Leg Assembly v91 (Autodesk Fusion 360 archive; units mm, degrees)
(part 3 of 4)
extrude "Extrude2" cut of existing geometry blind -29.21
extrude "Extrude6" new body sketch "Sketch6" profile of L3 L4 L5 L6 L9 L12 L10 L11 along normal blind 28.4988
work_plane "WorkPlane3" AlongDistance -1.6
split "Split2"
sketch "Sketch7" plane through (0, 0, 26.4) normal (0, 0, 1) x axis (-1, 0, 0)
  line L1 (0.8337, -23.6158) -> (0.8337, 14.8742)
  line L2 (-17.6263, -23.6158) -> (0.8337, -23.6158)
  line L3 (-17.6263, 14.8742) -> (-17.6263, -23.6158)
  line L4 (0.8337, 14.8742) -> (-17.6263, 14.8742)
  line L5 (4.0087, -26.7908) -> (-20.8013, -26.7908)
  line L6 (4.0087, 18.0492) -> (4.0087, -26.7908)
  line L7 (-20.8013, 18.0492) -> (4.0087, 18.0492)
  line L8 (-20.8013, -26.7908) -> (-20.8013, 18.0492)
  line L9 (-20.8013, 6.1292) -> (4.0087, 6.1292)
  line L10 (-20.8013, -1.8708) -> (4.0087, -1.8708)
  circle C1 centre (-8.3963, 6.1292) radius 8.5
  circle C2 centre (-8.3963, 6.1292) radius 8.75
  point P12 (4.0087, 6.1292)
  point P13 (-20.8013, 6.1292)
  point P14 (4.0087, -1.8708)
  point P15 (-20.8013, -1.8708)
  coincident L6 P12
  coincident L8 P13
  perpendicular L8 L9
  coincident L6 P14
  coincident L8 P15
  perpendicular L8 L10
  dimension "d48" = 0.25
  dimension "d51" distance L9 L10 = 8
extrude "Extrude7" add sketch "Sketch7" profile of L1 L3 L4 C2 L10 against normal blind 26.8988
extrude "Extrude8" cut sketch "Sketch7" profile of L4 C2 against normal blind 38.1
offset_faces "OffsetFaces1" distance 0.75
fillet "Fillet3" radius 1.651
split "Split3"
remove_body "RemoveBody5"
mirror "Mirror1" mirrorStitchTolerance 0.1016
combine "Combine2"
component_from_bodies "Body->Comp1"
copy_paste_bodies "CutPasteBodies1"
mirror "Mirror1" mirrorStitchTolerance 0.1016
align "Align1"
extrude "Extrude1" add of existing geometry blind 6.35
extrude "Extrude9" new body of existing geometry blind 19.9898
copy_paste_bodies "CutPasteBodies2"
copy_paste "CutPaste3"
copy_paste_bodies "CutPasteBodies2"
sketch "Sketch8" plane through (0, 0, 19.9956) normal (0, 0, -1) x axis (1, 0, 0)
  line L1 (0.3963, -22.3708) -> (0.3963, -3.3708)
  line L2 (16.3963, -22.3708) -> (0.3963, -22.3708)
  line L3 (16.3963, -3.3708) -> (16.3963, -22.3708)
  line L4 (0.3963, -3.3708) -> (16.3963, -3.3708)
  line L5 (1.5713, -6.5458) -> (1.5713, -21.1958)
  line L6 (15.2213, -6.5458) -> (1.5713, -6.5458)
  line L7 (15.2213, -21.1958) -> (15.2213, -6.5458)
  line L8 (1.5713, -21.1958) -> (15.2213, -21.1958)
  line L9 (-4.0087, 18.0492) -> (20.8013, 18.0492)
  line L10 (-4.0087, -26.7908) -> (-4.0087, 18.0492)
  line L11 (20.8013, -26.7908) -> (-4.0087, -26.7908)
  line L12 (20.8013, 18.0492) -> (20.8013, -26.7908)
  line L13 (16.8763, -22.8658) -> (16.8763, -3.2059)
  line L14 (-0.0837, -22.8658) -> (16.8763, -22.8658)
  line L15 (-0.0837, -3.2059) -> (-0.0837, -22.8658)
  circle C1 centre (8.3963, -14.6208) radius 8
  circle C2 centre (8.3963, -14.6208) radius 8
  arc A1 centre (8.3963, 6.1292) radius 8.75 clockwise from (1.4656, 0.788) to (15.327, 0.788)
  arc A2 centre (16.6347, -0.2198) radius 1.651 clockwise from (15.93, -1.7129) to (15.327, 0.788)
  arc A3 centre (15.2253, -3.2059) radius 1.651 clockwise from (15.93, -1.7129) to (16.8763, -3.2059)
  arc A4 centre (1.5673, -3.2059) radius 1.651 clockwise from (-0.0837, -3.2059) to (0.8626, -1.7129)
  arc A5 centre (0.1579, -0.2198) radius 1.651 clockwise from (1.4656, 0.788) to (0.8626, -1.7129)
  circle C3 centre (8.3963, 6.1292) radius 8.5
  circle C4 centre (8.3963, 6.1292) radius 8.75
  dimension "d72" = 0.25
extrude "Extrude10" new body sketch "Sketch8" profile of L1 L2 L3 L4 L5 L6 L7 L8 C1 C2 A2 A3 L13 L14 L15 A4 A5 C4 along normal blind 5.0038
sketch "Sketch9" plane through (0, 0, 14.9918) normal (0, 0, -1) x axis (1, 0, 0)
  line L1 (-0.0837, -22.8658) -> (-0.0837, -3.2059)
  line L2 (16.8763, -22.8658) -> (-0.0837, -22.8658)
  line L3 (16.8763, -3.2059) -> (16.8763, -22.8658)
  circle C1 centre (8.3963, -14.6208) radius 8
  arc A1 centre (15.2253, -3.2059) radius 1.651 clockwise from (15.93, -1.7129) to (16.8763, -3.2059)
  arc A2 centre (16.6347, -0.2198) radius 1.651 clockwise from (15.93, -1.7129) to (15.327, 0.788)
  arc A3 centre (8.3963, 6.1292) radius 8.75 clockwise from (15.327, 0.788) to (1.4656, 0.788)
  arc A4 centre (0.1579, -0.2198) radius 1.651 clockwise from (1.4656, 0.788) to (0.8626, -1.7129)
  arc A5 centre (1.5673, -3.2059) radius 1.651 clockwise from (-0.0837, -3.2059) to (0.8626, -1.7129)
  arc A6 centre (8.3963, 6.1292) radius 8.75 clockwise from (15.327, 0.788) to (1.4656, 0.788)
  arc A7 centre (8.3963, 6.1292) radius 11.1625 clockwise from (17.2379, -0.6847) to (-0.4452, -0.6847)
  dimension "d73" = 2.4125 (= "0.125 in - 0.0300196850393694 in")
extrude "Extrude11" add sketch "Sketch9" profile of A1 A2 A3 A4 A5 A6 A7 along normal blind 15.4906
combine "Combine3"
delete_face "DeleteFace1"
delete_face "DeleteFace2"
fillet "Fillet1" radius 4.7625
sketch "Sketch10" plane through (0, 0, 8.3168) normal (0, 0, -1) x axis (1, 0, 0)
  circle C1 centre (8.3963, -14.6208) radius 4
  circle C2 centre (8.3963, -14.6208) radius 8
  circle C3 centre (8.3963, -14.6208) radius 9.5875
  dimension "d78" = 1.5875 (= "( 1 / 16 ) * 1 in")
extrude "Extrude7" cut sketch "Sketch10" along normal blind 15.24 and against normal blind 6.6802
extrude "Extrude8" add of existing geometry blind 0.0052 (= "2.047E-04 in")
sketch "Sketch11" plane through (0, 0, 14.9918) normal (0, 0, -1) x axis (1, 0, 0)
  line L1 (16.8763, -22.8658) -> (13.2892, -22.8658)
  line L2 (16.8763, -19.0941) -> (16.8763, -22.8658)
  line L3 (16.8763, -9.3559) -> (16.8763, -10.1476)
  line L4 (-0.0837, -10.1476) -> (-0.0837, -9.3559)
  line L5 (-0.0837, -22.8658) -> (-0.0837, -19.0941)
  line L6 (3.5034, -22.8658) -> (-0.0837, -22.8658)
  circle C1 centre (8.3963, -14.6208) radius 8
  arc A1 centre (8.3963, -14.6208) radius 9.5875 clockwise from (16.8763, -10.1476) to (16.8763, -19.0941)
  arc A2 centre (12.1138, -9.3559) radius 4.7625 clockwise from (11.0021, -4.7249) to (16.8763, -9.3559)
  arc A3 centre (8.3963, 6.1292) radius 11.1625 clockwise from (11.0021, -4.7249) to (5.7906, -4.7249)
  arc A4 centre (4.6788, -9.3559) radius 4.7625 clockwise from (-0.0837, -9.3559) to (5.7906, -4.7249)
  arc A5 centre (8.3963, -14.6208) radius 9.5875 clockwise from (-0.0837, -19.0941) to (-0.0837, -10.1476)
  arc A6 centre (8.3963, -14.6208) radius 9.5875 clockwise from (13.2892, -22.8658) to (3.5034, -22.8658)
  circle C2 centre (8.3963, -14.6208) radius 9.5875
  dimension "d85" = 1.5875 (= "( 1 / 16 ) * 1 in")
extrude "Extrude9" add sketch "Sketch11" profile of L1 L2 L3 A2 A3 A4 L4 L5 L6 C2 along normal blind 15.494
extrude "Extrude10" cut of existing geometry blind -0.0034 (= "-1.339E-04 in")
extrude "Extrude3" cut of existing geometry blind -0.508
extrude "Extrude11" cut of existing geometry blind -0.508
extrude "Extrude4" cut of existing geometry blind -1
offset_faces "OffsetFaces1" distance 1.5875 (= "( 1 / 16 ) * 1 in")
split "Split2"
delete_face "DeleteFace3"
combine "Combine4"
split "Split3"
sketch "Sketch12" plane through (0, 0, 4.8168) normal (0, 0, 1) x axis (-1, 0, 0)
  line L1 (-4.6463, -6.3208) -> (-1.1463, -9.8208)
  line L2 (-12.1463, -6.3208) -> (-4.6463, -6.3208)
  line L3 (-15.6463, -9.8208) -> (-12.1463, -6.3208)
  line L4 (-15.6463, -13.7917) -> (-15.6463, -9.8208)
  line L5 (-15.6463, -19.8208) -> (-15.6463, -15.45)
  line L6 (-1.1463, -15.45) -> (-1.1463, -19.8208)
  line L7 (-1.1463, -9.8208) -> (-1.1463, -13.7917)
  line L8 (-12.1463, -6.3208) -> (-15.6463, -9.8208)
  line L9 (-4.6463, -6.3208) -> (-12.1463, -6.3208)
  line L10 (-4.6463, -6.3208) -> (-1.1463, -9.8208)
  line L11 (-15.6463, -9.8208) -> (-15.6463, -19.8208)
  line L12 (-1.1463, -9.8208) -> (-1.1463, -19.8208)
  line L13 (-0.8963, -9.7173) -> (-0.8963, -19.8925)
  line L14 (-4.5428, -6.0708) -> (-0.8963, -9.7173)
  line L15 (-4.5428, -6.0708) -> (-12.2499, -6.0708)
  line L16 (-12.2499, -6.0708) -> (-15.8963, -9.7173)
  line L17 (-15.8963, -9.7173) -> (-15.8963, -19.8925)
  arc A1 centre (-14.3963, -14.6208) radius 1.5 clockwise from (-15.6463, -13.7917) to (-15.6463, -15.45)
  arc A2 centre (-8.3963, -15.2505) radius 8.5703 clockwise from (-1.1463, -19.8208) to (-15.6463, -19.8208)
  arc A3 centre (-2.3963, -14.6208) radius 1.5 clockwise from (-1.1463, -15.45) to (-1.1463, -13.7917)
  arc A4 centre (-8.3963, -15.2505) radius 8.5703 clockwise from (-1.1463, -19.8208) to (-15.6463, -19.8208)
  arc A5 centre (-8.3963, -15.2505) radius 8.8203 clockwise from (-0.8963, -19.8925) to (-15.8963, -19.8925)
  circle C1 centre (-8.3963, -14.6208) radius 9.5875
  point P15 (-15.6463, -19.8208)
  point P22 (-15.6463, -19.8208)
  point P18 (-15.6463, -9.8208)
  point P23 (-15.6463, -9.8208)
  point P16 (-1.1463, -19.8208)
  point P24 (-1.1463, -19.8208)
  point P21 (-1.1463, -9.8208)
  point P25 (-1.1463, -9.8208)
  coincident P15 P22
  coincident P18 P23
  coincident P16 P24
  coincident P21 P25
  dimension "d97" = 0.25
extrude "Extrude12" add sketch "Sketch12" profile of A5 L13 L14 L15 L16 L17 C1 against normal blind 4.8006
extrude "Extrude13" add of existing geometry blind 0.007 (= "2.756E-04 in")
split "Split4"
delete_face "DeleteFace4"
delete_face "DeleteFace5"
combine "Combine5"
extrude "Extrude14" add of existing geometry blind 1.4986
extrude "Extrude15" add of existing geometry blind 0.0014 (= "5.512E-05 in")
sketch "Sketch13" plane through (0, 0, 6.3168) normal (0, 0, 1) x axis (-1, 0, 0)
  line L1 (-15.8963, -9.7173) -> (-15.8963, -19.8925)
  line L2 (-12.2499, -6.0708) -> (-15.8963, -9.7173)
  line L3 (-4.5428, -6.0708) -> (-12.2499, -6.0708)
  line L4 (-0.8963, -9.7173) -> (-4.5428, -6.0708)
  line L5 (-0.8963, -19.8925) -> (-0.8963, -9.7173)
  line L6 (5.5962, 19.6367) -> (5.5962, -28.3783)
  line L7 (-22.3888, 19.6367) -> (5.5962, 19.6367)
  line L8 (-22.3888, -28.3783) -> (-22.3888, 19.6367)
  line L9 (5.5962, -28.3783) -> (-22.3888, -28.3783)
  line L10 (-3.6338, -52.7208) -> (-13.1588, -52.7208)
  line L11 (-3.6338, 23.4792) -> (-3.6338, -52.7208)
  line L12 (-13.1588, 23.4792) -> (-3.6338, 23.4792)
  line L13 (-13.1588, -52.7208) -> (-13.1588, 23.4792)
  line L14 (-3.6338, 23.4792) -> (-13.1588, -52.7208)
  line L15 (-13.1588, 23.4792) -> (-3.6338, -52.7208)
  arc A1 centre (-8.3963, -15.2505) radius 8.8203 clockwise from (-0.8963, -19.8925) to (-15.8963, -19.8925)
  circle C1 centre (-8.3963, 6.1292) radius 8.75
  circle C2 centre (-8.3963, -14.6208) radius 4
  point P19 (-8.3963, -14.6208)
  point P14 (-8.3963, -14.6208)
  point P15 (-13.1588, -52.7208)
  point P16 (-3.6338, -52.7208)
  point P18 (-13.1588, 23.4792)
  horizontal L10
  perpendicular L10 L11
  parallel L10 L12
  parallel L11 L13
  coincident L14 P19
  coincident L15 P19
  coincident P14 P19
  dimension "d106" distance P15 P16 = 9.525
  dimension "d107" distance P15 P18 = 76.2
extrude "Extrude16" cut sketch "Sketch13" profile of A1 L9 L11 L13 against normal blind 3.2004
extrude "Extrude17" cut sketch "Sketch13" profile of L7 C1 L11 L13 against normal blind 5.3086
extrude "Extrude18" cut of existing geometry blind -0.0002 (= "-7.873E-06 in")
extrude "Extrude19" add of existing geometry blind 0.0004 (= "1.574E-05 in")
combine "Combine1"
offset_faces "OffsetFaces2" distance 0.7937 (= "( 1 / 32 ) * 1 in")
extrude "Extrude20" add of existing geometry blind 2.175 (= "0.125 in - 1 mm")
sketch "Sketch14" plane through (0, 0, 28) normal (0, 0, 1) x axis (-1, 0, 0)
  line L1 (0.8337, 14.8742) -> (-17.6263, 14.8742)
  line L2 (0.8337, -23.6158) -> (0.8337, 14.8742)
  line L3 (-17.6263, -23.6158) -> (0.8337, -23.6158)
  line L4 (-17.6263, 14.8742) -> (-17.6263, -23.6158)
  line L5 (-22.3888, -28.3783) -> (-22.3888, 19.6367)
  line L6 (5.5962, -28.3783) -> (-22.3888, -28.3783)
  line L7 (5.5962, 19.6367) -> (5.5962, -28.3783)
  line L8 (-22.3888, 19.6367) -> (5.5962, 19.6367)
  line L9 (-17.6963, 15.5831) -> (0.9037, 15.5831)
  line L10 (0.9037, 15.5831) -> (-17.6963, 15.5831)
  line L11 (-18.3963, -23.3708) -> (-18.3963, 14.6292)
  line L12 (-18.3963, -17.3601) -> (-18.3963, -23.3708)
  line L13 (-18.3963, -4.3708) -> (-18.3963, -17.3601)
  line L14 (-18.3963, 14.6292) -> (-18.3963, -4.3708)
  line L15 (1.6037, 14.6292) -> (1.6037, -23.3708)
  line L16 (1.6037, -4.3708) -> (1.6037, 14.6292)
  line L17 (1.6037, -17.3601) -> (1.6037, -4.3708)
  line L18 (1.6037, -23.3708) -> (1.6037, -17.3601)
  line L19 (-17.6963, -24.3248) -> (0.9037, -24.3248)
  line L20 (0.9037, -24.3248) -> (-17.6963, -24.3248)
  arc A1 centre (-17.3963, 14.6292) radius 1 clockwise from (-18.3963, 14.6292) to (-17.6963, 15.5831)
  arc A2 centre (-17.3963, 14.6292) radius 1 clockwise from (-18.3963, 14.6292) to (-17.6963, 15.5831)
  arc A3 centre (0.6037, 14.6292) radius 1 clockwise from (0.9037, 15.5831) to (1.6037, 14.6292)
  arc A4 centre (0.6037, 14.6292) radius 1 clockwise from (0.9037, 15.5831) to (1.6037, 14.6292)
  arc A5 centre (0.6037, -23.3708) radius 1 clockwise from (1.6037, -23.3708) to (0.9037, -24.3248)
  arc A6 centre (0.6037, -23.3708) radius 1 clockwise from (1.6037, -23.3708) to (0.9037, -24.3248)
  arc A7 centre (-17.3963, -23.3708) radius 1 clockwise from (-17.6963, -24.3248) to (-18.3963, -23.3708)
  arc A8 centre (-17.3963, -23.3708) radius 1 clockwise from (-17.6963, -24.3248) to (-18.3963, -23.3708)
extrude "Extrude21" add sketch "Sketch14" profile of L5 L6 L7 L8 A1 A2 L9 L10 L11 L12 L13 L14 A3 A4 L15 L16 L17 L18 A5 A6 L19 L20 A7 A8 along normal blind 13.0048
split "Split5"
extrude "Extrude22" add of existing geometry blind 2
remove_body "RemoveBody3"
copy_paste "CutPaste1"
copy_paste_bodies "CutPasteBodies1"
remove_instance "RemoveInstance2"
split "Split6"
remove_body "RemoveBody4"
combine "Combine1"
offset_faces "OffsetFaces3" distance 4.93 (= "0.1315944881889787 in + ( 1 / 16 ) * 1 in")
sketch "Sketch16" plane through (0, 0, 28) normal (0, 0, 1) x axis (-1, 0, 0)
  line L1 (5.5962, 24.5667) -> (5.5962, -33.3083)
  line L2 (-22.3888, 24.5667) -> (5.5962, 24.5667)
  line L3 (-22.3888, -33.3083) -> (-22.3888, 24.5667)
  line L4 (5.5962, -33.3083) -> (-22.3888, -33.3083)
  line L5 (0.8337, 14.8742) -> (-17.6263, 14.8742)
  line L6 (0.8337, -23.6158) -> (0.8337, 14.8742)
  line L7 (-17.6263, -23.6158) -> (0.8337, -23.6158)
  line L8 (-17.6263, 14.8742) -> (-17.6263, -23.6158)
  arc A1 centre (-3.4963, 20.4292) radius 2.1 clockwise from (-2.4963, 22.2758) to (-4.4963, 22.2758)
  circle C1 centre (-3.4963, 20.4292) radius 1.5
  concentric A1 C1
  dimension "d141" diameter C1 = 3
work_plane "WorkPlane5"
chamfer "Chamfer1" distance 6.35
split "Split7"
sketch "Sketch17" plane through (0, 0, 28) normal (0, 0, 1) x axis (-1, 0, 0)
  line L1 (0.8337, 14.8742) -> (-17.6263, 14.8742)
  line L2 (0.8337, -23.6158) -> (0.8337, 14.8742)
  line L3 (-17.6263, -23.6158) -> (0.8337, -23.6158)
  line L4 (-17.6263, 14.8742) -> (-17.6263, -23.6158)
  line L5 (5.5962, -26.9583) -> (-0.7538, -33.3083)
  line L6 (5.5962, 18.2167) -> (5.5962, -26.9583)
  line L7 (-0.7538, 24.5667) -> (5.5962, 18.2167)
  line L8 (-16.0388, 24.5667) -> (-0.7538, 24.5667)
  line L9 (-22.3888, 18.2167) -> (-16.0388, 24.5667)
  line L10 (-22.3888, -26.9583) -> (-22.3888, 18.2167)
  line L11 (-16.0388, -33.3083) -> (-22.3888, -26.9583)
  line L12 (-0.7538, -33.3083) -> (-16.0388, -33.3083)
  arc A1 centre (-3.4963, 20.4292) radius 2.1 clockwise from (-2.4963, 22.2758) to (-4.4963, 22.2758)
  circle C1 centre (-3.4963, 20.4292) radius 2.2
  concentric A1 C1
  dimension "d149" diameter C1 = 4.4
extrude "Extrude26" cut sketch "Sketch17" profile of C1 against normal blind 6
mirror "Mirror4" mirrorStitchTolerance 0.1016
mirror "Mirror5" mirrorStitchTolerance 0.1016
sketch "Sketch1" plane through (0, 0, 0) normal (0, 0, 1) x axis (1, 0, 0)
  circle C1 centre (0, 0) radius 2.45
  circle C2 centre (0, 0) radius 1.5
  circle C3 centre (0, 0) radius 1.95
  point P1 (0, 0)
  point P2 (0, 0)
  coincident P1 P2
  concentric C1 C2
  concentric C1 C3
  dimension "d1_2" diameter C1 = 4.9
  dimension "d2_2" diameter C2 = 3
  dimension "d3_2" diameter C3 = 3.9
extrude "Extrude1" new body sketch "Sketch1" distance 0.7 (= "( 1.4 / 2 ) * 1 mm") named "d4_2"
extrude "Extrude2" add sketch "Sketch1" profile of C2 C3 distance 3.3 (= "5 mm - 1.7 mm") named "d6_2"
extrude "Extrude3" of existing geometry blind 1.7 named "d9_2"
extrude "Extrude4" add of existing geometry blind 1.7 named "d11_2"
mirror "Mirror1" mirrorStitchTolerance 0.1 named "d14_1"
extrude "Extrude5" new body sketch "Sketch1" profile of C2 C3 distance 3 named "d15_1"
extrude "Extrude6" sketch "Sketch1" blind -1.8 named "d18_1"
mirror "Mirror2" mirrorStitchTolerance 0.1 named "d21_1"
move "Move1"
copy_paste "CutPaste4"
remove_body "RemoveBody1"
align "Align1"
mirror "Mirror3" mirrorStitchTolerance 0.1016
mirror "Mirror4" mirrorStitchTolerance 0.1016
base_feature "Base Feature1"
base_feature "Base Feature1"
base_feature "Base Feature1"
base_feature "Base Feature1"
base_feature "Base Feature1"
base_feature "Base Feature1"
copy_paste "CutPaste5"
remove_instance "RemoveInstance4"
align "Align1"
mirror "Mirror1" mirrorStitchTolerance 0.1016
mirror "Mirror2" mirrorStitchTolerance 0.1016
sketch "Sketch18" plane through (0, 0, -2.1658) normal (0, 0, -1) x axis (1, 0, 0)
  line L1 (0.7538, -33.3083) -> (-5.5962, -26.9583)
  line L2 (16.0388, -33.3083) -> (0.7538, -33.3083)
  line L3 (22.3888, -26.9583) -> (16.0388, -33.3083)
  line L4 (22.3888, 18.2167) -> (22.3888, -26.9583)
  line L5 (16.0388, 24.5667) -> (22.3888, 18.2167)
  line L6 (0.7538, 24.5667) -> (16.0388, 24.5667)
  line L7 (-5.5962, 18.2167) -> (0.7538, 24.5667)
  line L8 (-5.5962, -26.9583) -> (-5.5962, 18.2167)
  line L9 (-5.5962, -26.9583) -> (0.7538, -33.3083)
  line L10 (-5.5962, 18.2167) -> (-5.5962, -26.9583)
  line L11 (0.7538, 24.5667) -> (-5.5962, 18.2167)
  line L12 (3.6338, 24.5667) -> (0.7538, 24.5667)
  line L13 (3.6338, 13.4695) -> (3.6338, 24.5667)
  line L14 (13.1588, 24.5667) -> (13.1588, 13.4695)
  line L15 (16.0388, 24.5667) -> (13.1588, 24.5667)
  line L16 (22.3888, 18.2167) -> (16.0388, 24.5667)
  line L17 (22.3888, -26.9583) -> (22.3888, 18.2167)
  line L18 (16.0388, -33.3083) -> (22.3888, -26.9583)
  line L19 (13.1588, -33.3083) -> (16.0388, -33.3083)
  line L20 (13.1588, -22.6746) -> (13.1588, -33.3083)
  line L21 (15.8963, -9.7173) -> (15.8963, -19.8925)
  line L22 (12.2499, -6.0708) -> (15.8963, -9.7173)
  line L23 (4.5428, -6.0708) -> (12.2499, -6.0708)
  line L24 (0.8963, -9.7173) -> (4.5428, -6.0708)
  line L25 (0.8963, -19.8925) -> (0.8963, -9.7173)
  line L26 (3.6338, -33.3083) -> (3.6338, -22.6746)
  line L27 (0.7538, -33.3083) -> (3.6338, -33.3083)
  line L28 (-5.5962, -26.9583) -> (22.3888, 18.2167)
  line L29 (-5.5962, 18.2167) -> (22.3888, -26.9583)
  line L30 (-1.1287, -25.0083) -> (17.9213, -25.0083)
  line L31 (-1.1287, 16.2667) -> (-1.1287, -25.0083)
  line L32 (17.9213, 16.2667) -> (-1.1287, 16.2667)
  line L33 (17.9213, -25.0083) -> (17.9213, 16.2667)
  line L34 (-1.1287, 16.2667) -> (17.9213, -25.0083)
  line L35 (17.9213, 16.2667) -> (-1.1287, -25.0083)
  arc A1 centre (8.3963, 6.1292) radius 8.75 clockwise from (13.1588, 13.4695) to (3.6338, 13.4695)
  arc A2 centre (8.3963, -15.2505) radius 8.8203 clockwise from (15.8963, -19.8925) to (13.1588, -22.6746)
  arc A3 centre (8.3963, -15.2505) radius 8.8203 clockwise from (3.6338, -22.6746) to (0.8963, -19.8925)
  circle C1 centre (17.9213, 16.2667) radius 2.2
  point P20 (22.3888, 18.2167)
  point P34 (22.3888, 18.2167)
  point P11 (-5.5962, -26.9583)
  point P35 (-5.5962, -26.9583)
  point P21 (22.3888, -26.9583)
  point P36 (22.3888, -26.9583)
  point P12 (-5.5962, 18.2167)
  point P37 (-5.5962, 18.2167)
  point P38 (8.3963, -4.3708)
  point P43 (8.3963, -4.3708)
  point P42 (17.9213, 16.2667)
  point P44 (17.9213, 16.2667)
  point P39 (17.9213, -25.0083)
  point P41 (-1.1287, 16.2667)
  coincident P20 P34
  coincident P11 P35
  coincident P21 P36
  coincident P12 P37
  midpoint L29 P38
  horizontal L30
  perpendicular L30 L31
  parallel L30 L32
  parallel L31 L33
  coincident L34 P43
  coincident L35 P43
  coincident P38 P43
  coincident P42 P44
  dimension "d164" distance P39 P42 = 41.275
  dimension "d165" distance P41 P42 = 19.05
  dimension "d166" diameter C1 = 4.4
extrude "Extrude27" cut sketch "Sketch18" profile of C1 against normal blind 6
mirror "Mirror6" mirrorStitchTolerance 0.1016
mirror "Mirror7" mirrorStitchTolerance 0.1016
copy_paste_bodies "CopyPasteBodies1"
move "Move2"
align "Align2"
mirror "Mirror5" mirrorStitchTolerance 0.1016
mirror "Mirror6" mirrorStitchTolerance 0.1016
offset_faces "OffsetFaces4" distance 0.7937 (= "( 1 / 32 ) * 1 in")
delete_face "DeleteFace8"
delete_face "DeleteFace9"
delete_face "DeleteFace10"
delete_face "DeleteFace11"
delete_face "DeleteFace12"
delete_face "DeleteFace13"
delete_face "DeleteFace14"
delete_face "DeleteFace15"
chamfer "Chamfer2" distance 6.35
sketch "Sketch19" plane through (0, 0, 8.3168) normal (0, 0, 1) x axis (-1, 0, 0)
  line L1 (-16.8326, -34.1021) -> (-23.1826, -27.7521)
  line L2 (-13.1588, -34.1021) -> (-16.8326, -34.1021)
  line L3 (-13.1588, -22.6746) -> (-13.1588, -34.1021)
  line L4 (-15.8963, -9.7173) -> (-15.8963, -19.8925)
  line L5 (-12.2499, -6.0708) -> (-15.8963, -9.7173)
  line L6 (-4.5428, -6.0708) -> (-12.2499, -6.0708)
  line L7 (-0.8963, -9.7173) -> (-4.5428, -6.0708)
  line L8 (-0.8963, -19.8925) -> (-0.8963, -9.7173)
  line L9 (-3.6338, -34.1021) -> (-3.6338, -22.6746)
  line L10 (0.0399, -34.1021) -> (-3.6338, -34.1021)
  line L11 (6.3899, -27.7521) -> (0.0399, -34.1021)
  line L12 (6.3899, 19.0104) -> (6.3899, -27.7521)
  line L13 (0.0399, 25.3604) -> (6.3899, 19.0104)
  line L14 (-3.6338, 25.3604) -> (0.0399, 25.3604)
  line L15 (-3.6338, 13.4695) -> (-3.6338, 25.3604)
  line L16 (-13.1588, 25.3604) -> (-13.1588, 13.4695)
  line L17 (-16.8326, 25.3604) -> (-13.1588, 25.3604)
  line L18 (-23.1826, 19.0104) -> (-16.8326, 25.3604)
  line L19 (-23.1826, -27.7521) -> (-23.1826, 19.0104)
  line L20 (-14.7463, -14.6208) -> (-2.0463, -14.6208)
  arc A1 centre (-8.3963, -15.2505) radius 8.8203 clockwise from (-13.1588, -22.6746) to (-15.8963, -19.8925)
  arc A2 centre (-8.3963, -15.2505) radius 8.8203 clockwise from (-0.8963, -19.8925) to (-3.6338, -22.6746)
  arc A3 centre (-8.3963, 6.1292) radius 8.75 clockwise from (-3.6338, 13.4695) to (-13.1588, 13.4695)
  circle C1 centre (-8.3963, -14.6208) radius 4
  arc A4 centre (-7.6763, -14.8049) radius 9.6671 clockwise from (-15.8963, -19.8925) to (-15.8963, -9.7173)
  arc A5 centre (-9.1163, -14.8049) radius 9.6671 clockwise from (-0.8963, -9.7173) to (-0.8963, -19.8925)
  point P26 (-8.3963, -14.6208)
  point P29 (-8.3963, -14.6208)
  point P6 (-15.8963, -19.8925)
  point P31 (-15.8963, -19.8925)
  point P8 (-15.8963, -9.7173)
  point P30 (-15.8963, -9.7173)
  point P11 (-0.8963, -9.7173)
  point P34 (-0.8963, -9.7173)
  point P12 (-0.8963, -19.8925)
  point P33 (-0.8963, -19.8925)
  point P27 (-2.0463, -14.6208)
  point P28 (-14.7463, -14.6208)
  perpendicular L4 L20
  coincident P26 P29
  midpoint L20 P29
  coincident P6 P31
  coincident P8 P30
  coincident P11 P34
  coincident P12 P33
  tangent A1 A4
  tangent A2 A5
  dimension "d179" distance P27 P28 = 12.7
extrude "Extrude28" cut sketch "Sketch19" profile of L4 L8 A4 A5 against normal blind 2
sketch "Sketch20" plane through (0, 0, 26.4) normal (0, 0, 1) x axis (-1, 0, 0)
  line L1 (-17.6263, 14.8742) -> (-8.6921, 14.8742)
  line L2 (-17.6263, -23.6158) -> (-17.6263, 14.8742)
  line L3 (0.8337, -23.6158) -> (-17.6263, -23.6158)
  line L4 (0.8337, 14.8742) -> (0.8337, -23.6158)
  line L5 (-8.1005, 14.8742) -> (0.8337, 14.8742)
  line L6 (0.0837, -22.8658) -> (0.0837, -3.2059)
  line L7 (-16.8763, -22.8658) -> (0.0837, -22.8658)
  line L8 (-16.8763, -3.2059) -> (-16.8763, -22.8658)
  line L9 (-16.8763, 12.104) -> (-16.8763, -3.2059)
  line L10 (0.0837, 11.1729) -> (0.0837, -3.2059)
  arc A1 centre (-8.3963, 6.1292) radius 8.75 clockwise from (-8.1005, 14.8742) to (-1.4656, 0.788)
  arc A2 centre (-0.1579, -0.2198) radius 1.651 clockwise from (-0.8626, -1.7129) to (-1.4656, 0.788)
  arc A3 centre (-1.5673, -3.2059) radius 1.651 clockwise from (-0.8626, -1.7129) to (0.0837, -3.2059)
  arc A4 centre (-15.2253, -3.2059) radius 1.651 clockwise from (-16.8763, -3.2059) to (-15.93, -1.7129)
  arc A5 centre (-16.6347, -0.2198) radius 1.651 clockwise from (-15.327, 0.788) to (-15.93, -1.7129)
  arc A6 centre (-8.3963, 6.1292) radius 8.75 clockwise from (-15.327, 0.788) to (-8.6921, 14.8742)
  point P16 (-16.8763, -3.2059)
  point P21 (-16.8763, -3.2059)
  point P12 (0.0837, -3.2059)
  point P23 (0.0837, -3.2059)
  coincident P16 P21
  tangent A4 L9
  coincident P12 P23
  tangent A3 L10
extrude "Extrude29" cut sketch "Sketch20" profile of A1 A2 A3 A4 A5 A6 L9 L10 against normal blind 6.4008
extrude "Extrude30" cut of existing geometry blind -0.0036 (= "-1.417E-04 in")
component_from_bodies "Body->Comp1"
component_from_bodies "Body->Comp2"
component_from_bodies "Body->Comp3"
sketch "Sketch21" plane through (0, 0, 8.3168) normal (0, 0, 1) x axis (-1, 0, 0)
  line L1 (-3.6338, -34.1021) -> (-3.6338, -22.6746)
  line L2 (0.0399, -34.1021) -> (-3.6338, -34.1021)
  line L3 (6.3899, -27.7521) -> (0.0399, -34.1021)
  line L4 (6.3899, 19.0104) -> (6.3899, -27.7521)
  line L5 (0.0399, 25.3604) -> (6.3899, 19.0104)
  line L6 (-3.6338, 25.3604) -> (0.0399, 25.3604)
  line L7 (-3.6338, 13.4695) -> (-3.6338, 25.3604)
  line L8 (-13.1588, 25.3604) -> (-13.1588, 13.4695)
  line L9 (-16.8326, 25.3604) -> (-13.1588, 25.3604)
  line L10 (-23.1826, 19.0104) -> (-16.8326, 25.3604)
  line L11 (-23.1826, -27.7521) -> (-23.1826, 19.0104)
  line L12 (-16.8326, -34.1021) -> (-23.1826, -27.7521)
  line L13 (-13.1588, -34.1021) -> (-16.8326, -34.1021)
  line L14 (-13.1588, -22.6746) -> (-13.1588, -34.1021)
  line L15 (-12.2499, -6.0708) -> (-15.8963, -9.7173)
  line L16 (-4.5428, -6.0708) -> (-12.2499, -6.0708)
  line L17 (-0.8963, -9.7173) -> (-4.5428, -6.0708)
  line L18 (-0.8963, -9.7173) -> (-0.8963, -19.8925)
  line L19 (-4.5428, -6.0708) -> (-0.8963, -9.7173)
  line L20 (-12.2499, -6.0708) -> (-4.5428, -6.0708)
  line L21 (-15.8963, -9.7173) -> (-12.2499, -6.0708)
  line L22 (-15.8963, -19.8925) -> (-15.8963, -9.7173)
  line L23 (-13.1588, -34.1021) -> (-13.1588, -22.6746)
  line L24 (-3.6338, -34.1021) -> (-13.1588, -34.1021)
  line L25 (-3.6338, -22.6746) -> (-3.6338, -34.1021)
  arc A1 centre (-9.1163, -14.8049) radius 9.6671 clockwise from (-0.8963, -9.7173) to (-0.8963, -19.8925)
  arc A2 centre (-8.3963, -15.2505) radius 8.8203 clockwise from (-0.8963, -19.8925) to (-3.6338, -22.6746)
  arc A3 centre (-8.3963, 6.1292) radius 8.75 clockwise from (-3.6338, 13.4695) to (-13.1588, 13.4695)
  arc A4 centre (-8.3963, -15.2505) radius 8.8203 clockwise from (-13.1588, -22.6746) to (-15.8963, -19.8925)
  arc A5 centre (-7.6763, -14.8049) radius 9.6671 clockwise from (-15.8963, -19.8925) to (-15.8963, -9.7173)
  arc A6 centre (-8.3963, -15.2505) radius 8.5703 clockwise from (-1.1463, -19.8208) to (-15.6463, -19.8208)
  arc A7 centre (-8.3963, -15.2505) radius 8.8203 clockwise from (-3.6338, -22.6746) to (-13.1588, -22.6746)
  arc A8 centre (-8.3963, -15.2505) radius 8.8203 clockwise from (-13.1588, -22.6746) to (-15.8963, -19.8925)
  arc A9 centre (-8.3963, -15.2505) radius 8.8203 clockwise from (-0.8963, -19.8925) to (-3.6338, -22.6746)
  point P22 (-13.1588, -22.6746)
  point P32 (-13.1588, -22.6746)
  point P5 (-3.6338, -22.6746)
  point P31 (-3.6338, -22.6746)
  coincident P22 P32
  coincident P5 P31
  tangent A4 A7
extrude "Extrude1" add sketch "Sketch21" profile of L1 L14 A7 L23 L24 L25 against normal blind 5.207
move_face "MoveFace1"
position "Position5"
sketch "Sketch22" plane through (0, 0, 8.3168) normal (0, 0, 1) x axis (-1, 0, 0)
  line L1 (0.1537, -10.7673) -> (-3.4928, -7.1208)
  line L2 (0.1537, -18.4744) -> (0.1537, -10.7673)
  line L3 (-3.4928, -22.1208) -> (0.1537, -18.4744)
  line L4 (0.0399, -34.1021) -> (-16.8326, -34.1021)
  line L5 (6.3899, -27.7521) -> (0.0399, -34.1021)
  line L6 (6.3899, 19.0104) -> (6.3899, -27.7521)
  line L7 (0.0399, 25.3604) -> (6.3899, 19.0104)
  line L8 (-3.6338, 25.3604) -> (0.0399, 25.3604)
  line L9 (-3.6338, 13.4695) -> (-3.6338, 25.3604)
  line L10 (-13.1588, 25.3604) -> (-13.1588, 13.4695)
  line L11 (-16.8326, 25.3604) -> (-13.1588, 25.3604)
  line L12 (-23.1826, 19.0104) -> (-16.8326, 25.3604)
  line L13 (-23.1826, -27.7521) -> (-23.1826, 19.0104)
  line L14 (-16.8326, -34.1021) -> (-23.1826, -27.7521)
  line L15 (-10.2963, -17.1208) -> (-10.2963, -12.1208)
  line L16 (-6.4963, -17.1208) -> (-10.2963, -17.1208)
  line L17 (-6.4963, -12.1208) -> (-6.4963, -17.1208)
  line L18 (-10.2963, -12.1208) -> (-6.4963, -12.1208)
  line L19 (-3.6338, 25.3604) -> (-3.6338, 13.4695)
  line L20 (-13.1588, 25.3604) -> (-3.6338, 25.3604)
  line L21 (-13.1588, 13.4695) -> (-13.1588, 25.3604)
  line L22 (-6.4963, -12.1208) -> (-10.2963, -17.1208)
  line L23 (-6.4963, -17.1208) -> (-10.2963, -12.1208)
  line L24 (11.7059, -11.4458) -> (-28.4985, -11.4458)
  line L25 (11.7059, -17.7958) -> (11.7059, -11.4458)
  line L26 (-28.4985, -17.7958) -> (11.7059, -17.7958)
  line L27 (-28.4985, -11.4458) -> (-28.4985, -17.7958)
  line L28 (11.7059, -17.7958) -> (-28.4985, -11.4458)
  line L29 (-28.4985, -17.7958) -> (11.7059, -11.4458)
  line L30 (14.7067, 9.3042) -> (-31.4993, 9.3042)
  line L31 (14.7067, 2.9542) -> (14.7067, 9.3042)
  line L32 (-31.4993, 2.9542) -> (14.7067, 2.9542)
  line L33 (-31.4993, 9.3042) -> (-31.4993, 2.9542)
  line L34 (14.7067, 2.9542) -> (-31.4993, 9.3042)
  line L35 (-31.4993, 2.9542) -> (14.7067, 9.3042)
  arc A1 centre (-9.026, -14.6208) radius 8.8203 clockwise from (-13.668, -22.1208) to (-13.668, -7.1208)
  arc A2 centre (-8.5804, -15.3408) radius 9.6671 clockwise from (-13.668, -7.1208) to (-3.4928, -7.1208)
  arc A3 centre (-8.5804, -13.9008) radius 9.6671 clockwise from (-3.4928, -22.1208) to (-13.668, -22.1208)
  arc A4 centre (-8.3963, 6.1292) radius 8.75 clockwise from (-3.6338, 13.4695) to (-13.1588, 13.4695)
  arc A5 centre (-8.3963, 6.1292) radius 8.75 clockwise from (-3.6338, 13.4695) to (-13.1588, 13.4695)
  circle C1 centre (-8.3963, 6.1292) radius 8.75
  point P25 (-10.2963, -17.1208)
  point P33 (-10.2963, -17.1208)
  point P27 (-6.4963, -12.1208)
  point P34 (-6.4963, -12.1208)
  point P24 (-10.2963, -12.1208)
  point P35 (-10.2963, -12.1208)
  point P26 (-6.4963, -17.1208)
  point P36 (-6.4963, -17.1208)
  point P37 (-8.3963, -14.6208)
  point P42 (-8.3963, -14.6208)
  point P47 (-8.3963, 6.1292)
  point P30 (-8.3963, 6.1292)
  point P28 (-13.1588, 13.4695)
  point P43 (-31.4993, 9.3042)
  point P46 (-31.4993, 2.9542)
  point P38 (-28.4985, -11.4458)
  point P41 (-28.4985, -17.7958)
  coincident P25 P33
  coincident P27 P34
  coincident P24 P35
  coincident P26 P36
  midpoint L23 P37
  horizontal L24
  perpendicular L24 L25
  parallel L24 L26
  parallel L25 L27
  coincident L28 P42
  coincident L29 P42
  coincident P37 P42
  horizontal L30
  perpendicular L30 L31
  parallel L30 L32
  parallel L31 L33
  coincident L34 P47
  coincident L35 P47
  coincident P30 P47
  concentric A5 C1
  coincident P28 C1
  dimension "d189" distance P43 P46 = 6.35
  dimension "d190" distance P38 P41 = 6.35
extrude "Extrude2" add sketch "Sketch22" profile of L9 L10 L19 L20 L21 C1 against normal blind 7.3152
extrude "Extrude3" cut sketch "Sketch22" profile of A4 L13 A5 L30 L32 C1 against normal blind 7.3152
extrude "Extrude4" cut sketch "Sketch22" profile of A1 L13 L24 L26 against normal blind 5.207
extrude "Extrude5" add of existing geometry blind 0.0064 (= "2.520E-04 in")
extrude "Extrude6" add of existing geometry blind 0.007 (= "2.756E-04 in")
sketch "Sketch23" plane through (0, 0, 8.3168) normal (0, 0, 1) x axis (-1, 0, 0)
  line L1 (-23.1826, 2.9542) -> (-16.55, 2.9542)
  line L2 (-23.1826, -11.4458) -> (-23.1826, 2.9542)
  line L3 (-17.255, -11.4458) -> (-23.1826, -11.4458)
  line L4 (0.1537, -10.7673) -> (-3.4928, -7.1208)
  line L5 (0.1537, -18.4744) -> (0.1537, -10.7673)
  line L6 (-3.4928, -22.1208) -> (0.1537, -18.4744)
  line L7 (-23.1826, -17.7958) -> (-17.255, -17.7958)
  line L8 (-23.1826, -27.7521) -> (-23.1826, -17.7958)
  line L9 (-16.8326, -34.1021) -> (-23.1826, -27.7521)
  line L10 (0.0399, -34.1021) -> (-16.8326, -34.1021)
  line L11 (6.3899, -27.7521) -> (0.0399, -34.1021)
  line L12 (6.3899, 19.0104) -> (6.3899, -27.7521)
  line L13 (0.0399, 25.3604) -> (6.3899, 19.0104)
  line L14 (-16.8326, 25.3604) -> (0.0399, 25.3604)
  line L15 (-23.1826, 19.0104) -> (-16.8326, 25.3604)
  line L16 (-23.1826, 9.3042) -> (-23.1826, 19.0104)
  line L17 (-16.55, 9.3042) -> (-23.1826, 9.3042)
  line L18 (6.3899, -27.7521) -> (0.0399, -34.1021)
  line L19 (6.3899, 19.0104) -> (6.3899, -27.7521)
  line L20 (0.0399, 25.3604) -> (6.3899, 19.0104)
  line L21 (-16.8326, 25.3604) -> (0.0399, 25.3604)
  line L22 (-23.1826, 19.0104) -> (-16.8326, 25.3604)
  line L23 (-23.1826, -27.7521) -> (-23.1826, 19.0104)
  line L24 (-16.8326, -34.1021) -> (-23.1826, -27.7521)
  line L25 (0.0399, -34.1021) -> (-16.8326, -34.1021)
  line L26 (0.8337, 14.8742) -> (-17.6263, 14.8742)
  line L27 (0.8337, -23.6158) -> (0.8337, 14.8742)
  line L28 (-17.6263, -23.6158) -> (0.8337, -23.6158)
  line L29 (-17.6263, 14.8742) -> (-17.6263, -23.6158)
  arc A1 centre (-8.3963, 6.1292) radius 8.75 clockwise from (-16.55, 9.3042) to (-16.55, 2.9542)
  arc A2 centre (-9.026, -14.6208) radius 8.8203 clockwise from (-17.255, -11.4458) to (-13.668, -7.1208)
  arc A3 centre (-8.5804, -15.3408) radius 9.6671 clockwise from (-13.668, -7.1208) to (-3.4928, -7.1208)
  arc A4 centre (-8.5804, -13.9008) radius 9.6671 clockwise from (-3.4928, -22.1208) to (-13.668, -22.1208)
  arc A5 centre (-9.026, -14.6208) radius 8.8203 clockwise from (-13.668, -22.1208) to (-17.255, -17.7958)
  circle C1 centre (-3.4963, 20.4292) radius 2.2
  circle C2 centre (-13.2963, 20.4292) radius 2.2
  circle C3 centre (-3.4963, -29.1708) radius 2.2
  circle C4 centre (-13.2963, -29.1708) radius 2.2
extrude "Extrude7" cut sketch "Sketch23" profile of C1 C2 C3 C4 against normal blind 6
delete_face "DeleteFace1"
remove_body "RemoveBody2"
remove_body "RemoveBody3"
remove_body "RemoveBody4"
remove_body "RemoveBody5"
delete_face "DeleteFace1"
delete_face "DeleteFace2"
delete_face "DeleteFace3"
delete_face "DeleteFace4"
position "Position6"
sketch "Sketch24" plane through (0, 0, 28) normal (0, 0, 1) x axis (-1, 0, 0)
  line L1 (6.3899, -27.7521) -> (0.0399, -34.1021)
  line L2 (6.3899, 19.0104) -> (6.3899, -27.7521)
  line L3 (0.0399, 25.3604) -> (6.3899, 19.0104)
  line L4 (-16.8326, 25.3604) -> (0.0399, 25.3604)
  line L5 (-23.1826, 19.0104) -> (-16.8326, 25.3604)
  line L6 (-23.1826, -27.7521) -> (-23.1826, 19.0104)
  line L7 (-16.8326, -34.1021) -> (-23.1826, -27.7521)
  line L8 (0.0399, -34.1021) -> (-16.8326, -34.1021)
  line L9 (0.8337, 14.8742) -> (-17.6263, 14.8742)
  line L10 (0.8337, -23.6158) -> (0.8337, 14.8742)
  line L11 (-17.6263, -23.6158) -> (0.8337, -23.6158)
  line L12 (-17.6263, 14.8742) -> (-17.6263, -23.6158)
  circle C1 centre (-3.4963, -29.1708) radius 1.5
  circle C2 centre (-3.4963, -29.1708) radius 1.5
  concentric C1 C2
  dimension "d205" diameter C2 = 3
extrude "Extrude1" cut sketch "Sketch24" profile of C2 against normal blind 43.18
mirror "Mirror1" mirrorStitchTolerance 0.1016
mirror "Mirror2" mirrorStitchTolerance 0.1016
extrude "Extrude8" cut of existing geometry blind -25.4
sketch "Sketch1" plane through (0, 0, 0) normal (0, 0, 1) x axis (1, 0, 0)
  circle C1 centre (0, 0) radius 2.45
  circle C2 centre (0, 0) radius 1.5
  circle C3 centre (0, 0) radius 1.95
  point P1 (0, 0)
  point P2 (0, 0)
  coincident P1 P2
  concentric C1 C2
  concentric C1 C3
  dimension "d1_3" diameter C1 = 4.9
  dimension "d2_3" diameter C2 = 3
  dimension "d3_3" diameter C3 = 3.9
extrude "Extrude1" new body sketch "Sketch1" distance 0.7 (= "( 1.4 / 2 ) * 1 mm") named "d4_3"
extrude "Extrude2" add sketch "Sketch1" profile of C2 C3 distance 3.3 (= "5 mm - 1.7 mm") named "d6_3"
extrude "Extrude3" of existing geometry blind 1.7 named "d9_3"
extrude "Extrude4" add of existing geometry blind 1.7 named "d11_3"
mirror "Mirror1" mirrorStitchTolerance 0.1 named "d14_2"
extrude "Extrude5" new body sketch "Sketch1" profile of C2 C3 distance 3 named "d15_2"
extrude "Extrude6" sketch "Sketch1" blind -1.8 named "d18_2"
mirror "Mirror2" mirrorStitchTolerance 0.1 named "d21_2"
move "Move1"
remove_body "RemoveBody1"
extrude "Extrude9" cut of existing geometry blind -0.4826 (= "10 mm - 0.4127007874015741 in")
position "Position7"
mirror "Mirror3" mirrorStitchTolerance 0.1016
mirror "Mirror4" mirrorStitchTolerance 0.1016
copy_paste "CutPaste6"
offset_faces "OffsetFaces1" distance -3.175
delete_face "DeleteFace2"
delete_face "DeleteFace3"
delete_face "DeleteFace4"
chamfer "Chamfer1" distance 4.7625
remove_instance "RemoveInstance1"
offset_faces "OffsetFaces2" distance -0.2
sketch "Sketch25" plane through (0, 0, 1.008) normal (0, 0, 1) x axis (-1, 0, 0)
  line L1 (-20.0076, 9.3042) -> (-16.55, 9.3042)
  line L2 (-20.0076, 2.9542) -> (-20.0076, 9.3042)
  line L3 (-16.55, 2.9542) -> (-20.0076, 2.9542)
  line L4 (-20.0076, -11.4458) -> (-17.255, -11.4458)
  line L5 (-20.0076, -17.7958) -> (-20.0076, -11.4458)
  line L6 (-17.255, -17.7958) -> (-20.0076, -17.7958)
  line L7 (-3.4928, -22.1208) -> (-13.668, -22.1208)
  line L8 (0.1537, -18.4744) -> (-3.4928, -22.1208)
  line L9 (0.1537, -10.7673) -> (0.1537, -18.4744)
  line L10 (-3.4928, -7.1208) -> (0.1537, -10.7673)
  line L11 (-13.668, -7.1208) -> (-3.4928, -7.1208)
  line L12 (-20.0076, -17.7958) -> (-17.255, -17.7958)
  line L13 (-20.0076, -11.4458) -> (-20.0076, -17.7958)
  line L14 (-17.255, -11.4458) -> (-20.0076, -11.4458)
  line L15 (-17.255, -17.7958) -> (-17.255, -11.4458)
  line L16 (-20.0076, 2.9542) -> (-16.55, 2.9542)
  line L17 (-20.0076, 9.3042) -> (-20.0076, 2.9542)
  line L18 (-16.55, 9.3042) -> (-20.0076, 9.3042)
  line L19 (-16.55, 2.9542) -> (-16.55, 9.3042)
  arc A1 centre (-8.3963, 6.1292) radius 8.75 clockwise from (-16.55, 9.3042) to (-16.55, 2.9542)
  arc A2 centre (-9.026, -14.6208) radius 8.8203 clockwise from (-17.255, -11.4458) to (-13.668, -7.1208)
  arc A3 centre (-9.026, -14.6208) radius 8.8203 clockwise from (-13.668, -22.1208) to (-17.255, -17.7958)
  point P10 (-20.0076, -11.4458)
  point P20 (-20.0076, -11.4458)
  point P12 (-17.255, -17.7958)
  point P18 (-17.255, -17.7958)
  point P5 (-20.0076, 9.3042)
  point P24 (-20.0076, 9.3042)
  point P2 (-16.55, 2.9542)
  point P22 (-16.55, 2.9542)
  horizontal L12
  vertical L13
  horizontal L14
  vertical L15
  coincident P10 P20
  coincident P12 P18
  horizontal L16
  vertical L17
  horizontal L18
  vertical L19
  coincident P5 P24
  coincident P2 P22
extrude "Extrude10" cut sketch "Sketch25" profile of L1 L2 L3 L16 L17 L18 L19 against normal blind 8.89
extrude "Extrude11" cut sketch "Sketch25" profile of L4 L5 L6 L12 L13 L14 L15 distance 11.43
copy_paste "CutPaste1"
remove_instance "RemoveInstance8"
sketch "Sketch1" plane through (0, 0, 0) normal (0, 0, 1) x axis (1, 0, 0)
  line L1 (-7.25, -8.75) -> (7.25, -8.75)
  line L2 (-7.25, 8.75) -> (-7.25, -8.75)
  line L3 (7.25, 8.75) -> (-7.25, 8.75)
  line L4 (7.25, -8.75) -> (7.25, 8.75)
  line L5 (-7.25, 8.75) -> (7.25, -8.75)
  line L6 (7.25, 8.75) -> (-7.25, -8.75)
  line L7 (0, 8.75) -> (0, -8.75)
  line L8 (-2.5, -2.35) -> (2.5, -2.35)
  line L9 (-2.5, 1.45) -> (-2.5, -2.35)
  line L10 (2.5, 1.45) -> (-2.5, 1.45)
  line L11 (2.5, -2.35) -> (2.5, 1.45)
  line L12 (-2.5, 1.45) -> (2.5, -2.35)
  line L13 (2.5, 1.45) -> (-2.5, -2.35)
  line L14 (7.25, -0.45) -> (-7.25, -0.45)
  line L15 (3.75, -8.75) -> (7.25, -5.25)
  line L16 (-3.75, -8.75) -> (-7.25, -5.25)
  arc A1 centre (0, 0.1797) radius 8.5703 clockwise from (-7.25, 4.75) to (7.25, 4.75)
  circle C1 centre (6, -0.45) radius 1.5
  circle C2 centre (-6, -0.45) radius 1.5
  point P6 (0, 0)
  point P1 (0, 0)
  point P7 (0, -8.75)
  point P8 (0, 8.75)
  point P13 (0, -0.45)
  point P14 (-7.25, -0.45)
  point P15 (7.25, -0.45)
  point P16 (7.25, 4.75)
  point P17 (-7.25, 4.75)
  point P19 (7.25, 4.75)
  point P18 (-7.25, 4.75)
  point P21 (7.25, -5.25)
  point P22 (3.75, -8.75)
  point P23 (7.25, -5.25)
  point P24 (3.75, -8.75)
  point P25 (-7.25, -5.25)
  point P26 (-3.75, -8.75)
  point P27 (6, -0.45)
  point P2 (7.25, -8.75)
  point P5 (7.25, 8.75)
  horizontal L1
  perpendicular L1 L2
  parallel L1 L3
  parallel L2 L4
  coincident L5 P6
  coincident L6 P6
  coincident P1 P6
  midpoint L1 P7
  midpoint L3 P8
  horizontal L8
  perpendicular L8 L9
  parallel L8 L10
  parallel L9 L11
  coincident L12 P13
  coincident L13 P13
  coincident L7 P13
  coincident L2 P14
  coincident L4 P15
  perpendicular L4 L14
  coincident P13 L14
  coincident L4 P16
  symmetric L7 P16 P17
  coincident P8 A1
  tangent L3 A1
  coincident P16 P19
  coincident P17 P18
  coincident L4 P21
  coincident L1 P22
  coincident P21 P23
  coincident P22 P24
  symmetric L7 P23 P25
  symmetric L7 P24 P26
  coincident L14 P27
  symmetric L7 C1 C2
  dimension "d1_4" distance P2 P5 = 17.5
  dimension "d2_4" distance L2 L4 = 14.5
  dimension "d3_4" distance L1 L8 = 6.4
  dimension "d4_4" distance L3 L10 = 7.3
  dimension "d5_4" distance L9 L11 = 5
  dimension "d6_4" distance P5 P16 = 4
  dimension "d7_4" distance P2 P21 = 3.5
  dimension "d8_4" distance P2 P22 = 3.5
  dimension "d9_4" diameter C1 = 3
  dimension "d10_4" distance L11 P27 = 3.5 (= "2 mm + 1.5 mm")
extrude "Extrude1" new body sketch "Sketch1" profile of L1 L2 L4 L8 L9 L10 L11 A1 L15 L16 C1 C2 against normal blind 1.7 named "d11_4"
extrude "Extrude2" new body sketch "Sketch1" profile of L8 L9 L10 L11 along normal blind 1.5 named "d13_4"
sketch "Sketch2" plane through (0, 0, 0) normal (0, 0, 1) x axis (-1, 0, 0)
  line L1 (3.75, 8.75) -> (7.25, 5.25)
  line L2 (-3.75, 8.75) -> (3.75, 8.75)
  line L3 (-7.25, 5.25) -> (-3.75, 8.75)
  line L4 (-7.25, 1.2792) -> (-7.25, 5.25)
  line L5 (-7.25, -4.75) -> (-7.25, -0.3792)
  line L6 (7.25, -0.3792) -> (7.25, -4.75)
  line L7 (7.25, 5.25) -> (7.25, 1.2792)
  line L8 (2.5, -1.45) -> (-2.5, -1.45)
  line L9 (2.5, 2.35) -> (2.5, -1.45)
  line L10 (-2.5, 2.35) -> (2.5, 2.35)
  line L11 (-2.5, -1.45) -> (-2.5, 2.35)
  line L12 (2.5, 2.35) -> (-2.5, -1.45)
  line L13 (2.5, -1.45) -> (-2.5, 2.35)
  line L14 (11.5, 11.95) -> (-11.5, 11.95)
  line L15 (11.5, -11.05) -> (11.5, 11.95)
  line L16 (-11.5, -11.05) -> (11.5, -11.05)
  line L17 (-11.5, 11.95) -> (-11.5, -11.05)
  line L18 (11.5, -11.05) -> (-11.5, 11.95)
  line L19 (-11.5, -11.05) -> (11.5, 11.95)
  line L20 (8.5, 8.95) -> (-8.5, 8.95)
  line L21 (8.5, -8.05) -> (8.5, 8.95)
  line L22 (-8.5, -8.05) -> (8.5, -8.05)
  line L23 (-8.5, 8.95) -> (-8.5, -8.05)
  line L24 (8.5, -8.05) -> (-8.5, 8.95)
  line L25 (-8.5, -8.05) -> (8.5, 8.95)
  arc A1 centre (-6, 0.45) radius 1.5 clockwise from (-7.25, 1.2792) to (-7.25, -0.3792)
  arc A2 centre (0, -0.1797) radius 8.5703 clockwise from (7.25, -4.75) to (-7.25, -4.75)
  arc A3 centre (6, 0.45) radius 1.5 clockwise from (7.25, -0.3792) to (7.25, 1.2792)
  circle C1 centre (-8.5, 8.95) radius 1.5
  point P15 (-2.5, -1.45)
  point P19 (-2.5, -1.45)
  point P17 (2.5, 2.35)
  point P20 (2.5, 2.35)
  point P18 (-2.5, 2.35)
  point P21 (-2.5, 2.35)
  point P16 (2.5, -1.45)
  point P22 (2.5, -1.45)
  point P27 (0, 0.45)
  point P32 (0, 0.45)
  point P28 (-8.5, 8.95)
  point P33 (-8.5, 8.95)
  point P25 (11.5, -11.05)
  point P26 (-11.5, -11.05)
  point P24 (11.5, 11.95)
  point P29 (8.5, 8.95)
  point P31 (-8.5, -8.05)
  coincident P15 P19
  coincident P17 P20
  coincident P18 P21
  coincident P16 P22
  horizontal L14
  perpendicular L14 L15
  parallel L14 L16
  parallel L15 L17
  coincident L18 P27
  coincident L19 P27
  midpoint L12 P27
  horizontal L20
  perpendicular L20 L21
  parallel L20 L22
  parallel L21 L23
  coincident L24 P32
  coincident L25 P32
  coincident P27 P32
  coincident P28 P33
  dimension "d15_3" distance P25 P26 = 23
  dimension "d16_3" distance P24 P25 = 23
  dimension "d21_3" distance P28 P29 = 17
  dimension "d22_1" distance P28 P31 = 17
  dimension "d23_1" diameter C1 = 3
extrude "Extrude3" add sketch "Sketch2" profile of L1 L2 L3 L4 A1 L5 A2 L6 A3 L7 L8 L9 L10 L11 L14 L15 L16 L17 against normal blind 1.7 named "d17_3"
fillet "Fillet1" radius 3 named "d20_3"
extrude "Extrude4" cut sketch "Sketch2" profile of C1 against normal blind 5 named "d24_1"
work_axis "WorkAxis1" sketch "Sketch2"
circular_pattern "C-Pattern1" TotalAngle 360 named "d27_1"
copy_paste "CutPaste7"
copy_paste_bodies "CopyPasteBodies1"
component_from_bodies "Body->Comp2"
copy_paste "CutPaste1"
sketch "Sketch26" plane through (0, 0, 3.1168) normal (0, 0, 1) x axis (-1, 0, 0)
  line L1 (-17.255, -17.7958) -> (-17.255, -11.4458)
  line L2 (-3.4928, -22.1208) -> (-13.668, -22.1208)
  line L3 (0.1537, -18.4744) -> (-3.4928, -22.1208)
  line L4 (0.1537, -10.7673) -> (0.1537, -18.4744)
  line L5 (-3.4928, -7.1208) -> (0.1537, -10.7673)
  line L6 (-13.668, -7.1208) -> (-3.4928, -7.1208)
  line L7 (-10.2963, -17.1208) -> (-10.2963, -12.1208)
  line L8 (-6.4963, -17.1208) -> (-10.2963, -17.1208)
  line L9 (-6.4963, -12.1208) -> (-6.4963, -17.1208)
  line L10 (-10.2963, -12.1208) -> (-6.4963, -12.1208)
  line L11 (-6.4963, -12.1208) -> (-10.2963, -17.1208)
  line L12 (-10.2963, -12.1208) -> (-6.4963, -17.1208)
  line L13 (6.8437, -26.1208) -> (-23.6363, -26.1208)
  line L14 (6.8437, -3.1208) -> (6.8437, -26.1208)
  line L15 (-23.6363, -3.1208) -> (6.8437, -3.1208)
  line L16 (-23.6363, -26.1208) -> (-23.6363, -3.1208)
  line L17 (6.8437, -3.1208) -> (-23.6363, -26.1208)
  line L18 (-23.6363, -3.1208) -> (6.8437, -26.1208)
  line L19 (-23.8863, -26.3708) -> (-23.8863, -2.8708)
  line L20 (7.0937, -26.3708) -> (-23.8863, -26.3708)
  line L21 (7.0937, -2.8708) -> (7.0937, -26.3708)
  line L22 (-23.8863, -2.8708) -> (7.0937, -2.8708)
  line L23 (-3.6338, -9.3883) -> (-13.1588, -9.3883)
  line L24 (-3.6338, 21.6466) -> (-3.6338, -9.3883)
  line L25 (-13.1588, 21.6466) -> (-3.6338, 21.6466)
  line L26 (-13.1588, -9.3883) -> (-13.1588, 21.6466)
  line L27 (-3.6338, 21.6466) -> (-13.1588, -9.3883)
  line L28 (-13.1588, 21.6466) -> (-3.6338, -9.3883)
  line L29 (-2.7026, -22.1208) -> (-4.2901, -22.1208)
  line L30 (-2.7026, -36.2208) -> (-2.7026, -22.1208)
  line L31 (-4.2901, -36.2208) -> (-2.7026, -36.2208)
  line L32 (-4.2901, -22.1208) -> (-4.2901, -36.2208)
  line L33 (-2.7026, -36.2208) -> (-4.2901, -22.1208)
  line L34 (-4.2901, -36.2208) -> (-2.7026, -22.1208)
  line L35 (-12.5026, -24.395) -> (-14.0901, -24.395)
  line L36 (-12.5026, -33.9467) -> (-12.5026, -24.395)
  line L37 (-14.0901, -33.9467) -> (-12.5026, -33.9467)
  line L38 (-14.0901, -24.395) -> (-14.0901, -33.9467)
  line L39 (-12.5026, -33.9467) -> (-14.0901, -24.395)
  line L40 (-14.0901, -33.9467) -> (-12.5026, -24.395)
  arc A1 centre (-9.026, -14.6208) radius 8.8203 clockwise from (-13.668, -22.1208) to (-17.255, -17.7958)
  arc A2 centre (-9.026, -14.6208) radius 8.8203 clockwise from (-17.255, -11.4458) to (-13.668, -7.1208)
  circle C1 centre (-3.4963, -29.1708) radius 2.2
  arc A3 centre (-8.3963, 6.1292) radius 8.75 clockwise from (-16.55, 9.3042) to (-16.55, 2.9542)
  circle C2 centre (-13.2963, -29.1708) radius 2.2
  point P12 (-10.2963, -17.1208)
  point P15 (-10.2963, -17.1208)
  point P14 (-6.4963, -12.1208)
  point P16 (-6.4963, -12.1208)
  point P13 (-6.4963, -17.1208)
  point P17 (-6.4963, -17.1208)
  point P11 (-10.2963, -12.1208)
  point P18 (-10.2963, -12.1208)
  point P19 (-8.3963, -14.6208)
  point P24 (-8.3963, -14.6208)
  point P37 (-8.3963, 6.1292)
  point P32 (-8.3963, 6.1292)
  point P38 (-4.2901, -22.1208)
  point P42 (-3.4963, -29.1708)
  point P25 (-3.4963, -29.1708)
  point P48 (-13.2963, -29.1708)
  point P43 (-13.2963, -29.1708)
  point P21 (6.8437, -26.1208)
  point P22 (6.8437, -3.1208)
  point P20 (-23.6363, -26.1208)
  point P33 (-13.1588, -9.3883)
  point P34 (-3.6338, -9.3883)
  point P46 (-12.5026, -33.9467)
  point P47 (-14.0901, -33.9467)
  point P40 (-2.7026, -36.2208)
  point P41 (-4.2901, -36.2208)
  coincident P12 P15
  coincident P14 P16
  coincident P13 P17
  coincident P11 P18
  midpoint L12 P19
  horizontal L13
  perpendicular L13 L14
  parallel L13 L15
  parallel L14 L16
  coincident L17 P24
  coincident L18 P24
  coincident P19 P24
  horizontal L23
  perpendicular L23 L24
  parallel L23 L25
  parallel L24 L26
  coincident L27 P37
  coincident L28 P37
  coincident P32 P37
  horizontal L29
  perpendicular L29 L30
  parallel L29 L31
  parallel L30 L32
  coincident L2 P38
  coincident L33 P42
  coincident L34 P42
  coincident P25 P42
  horizontal L35
  perpendicular L35 L36
  parallel L35 L37
  parallel L36 L38
  coincident L39 P48
  coincident L40 P48
  coincident P43 P48
  dimension "d229" distance P21 P22 = 23
  dimension "d230" distance P20 P21 = 30.48
  dimension "d231" = 0.25
  dimension "d232" distance P33 P34 = 9.525
  dimension "d235" distance P46 P47 = 1.5875 (= "( 1 / 16 ) * 1 in")
  dimension "d236" distance P40 P41 = 1.5875 (= "( 1 / 16 ) * 1 in")
extrude "Extrude1" cut sketch "Sketch26" profile of L1 A1 L2 L3 L4 L5 L6 A2 C1 L19 L20 L21 L22 A3 L23 L24 L26 L29 L30 L32 C2 L35 L36 L38 along normal blind 11.43
position "Position9"
extrude "Extrude2" add of existing geometry blind 11.938
copy_paste "CutPaste1"
copy_paste "CutPaste2"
